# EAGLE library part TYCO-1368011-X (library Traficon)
CT: Connector to replace the 2_stacked_rj45_w_leds (12/03/2008)
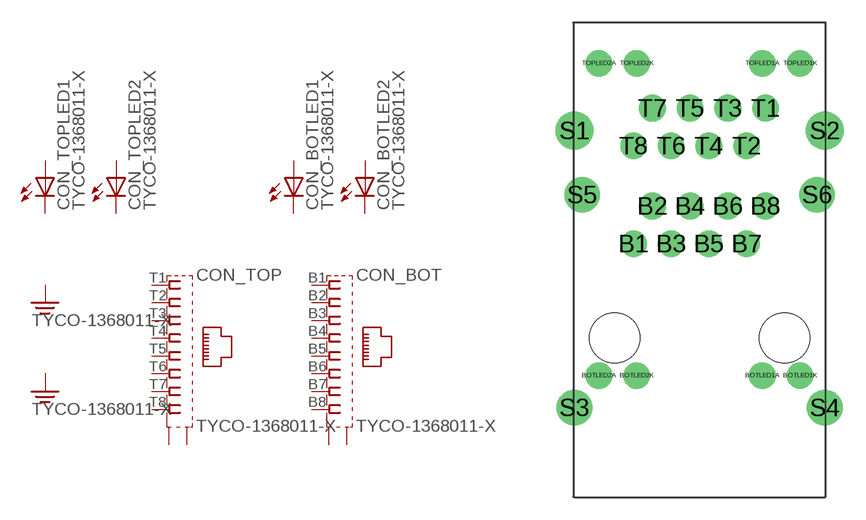
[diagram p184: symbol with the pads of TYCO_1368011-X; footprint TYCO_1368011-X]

Designator prefix CON; gates _BOT=JACK8SH _TOP=JACK8SH _TOPLED1=LED-1 _TOPLED2=LED-1 _BOTLED1=LED-1 _BOTLED2=LED-1 _SH1=PE _SH2=PE

## TYCO-1368011-X  [TYCO_1368011-X]
B1  _BOT:1  pas
B2  _BOT:2  pas
B3  _BOT:3  pas
B4  _BOT:4  pas
B5  _BOT:5  pas
B6  _BOT:6  pas
B7  _BOT:7  pas
B8  _BOT:8  pas
BOTLED1A  _BOTLED1:A  pas
BOTLED1K  _BOTLED1:C  pas
BOTLED2A  _BOTLED2:A  pas
BOTLED2K  _BOTLED2:C  pas
S1  _BOT:S1  pas
S2  _BOT:S2  pas
S3  _TOP:S1  pas
S4  _TOP:S2  pas
T1  _TOP:1  pas
T2  _TOP:2  pas
T3  _TOP:3  pas
T4  _TOP:4  pas
T5  _TOP:5  pas
T6  _TOP:6  pas
T7  _TOP:7  pas
T8  _TOP:8  pas
TOPLED1A  _TOPLED1:A  pas
TOPLED1K  _TOPLED1:C  pas
TOPLED2A  _TOPLED2:A  pas
TOPLED2K  _TOPLED2:C  pas

## Footprint TYCO_1368011-X (pad centres in mm)
drill 1.2 round: B1 1.265,6.35; B2 2.535,8.89; B3 3.805,6.35; B4 5.075,8.89; B5 6.345,6.35; B6 7.615,8.89; B7 8.885,6.35; B8 10.155,8.89; BOTLED1A 9.95,-2.54; BOTLED1K 12.49,-2.54; BOTLED2A -1.06,-2.54; BOTLED2K 1.48,-2.54; T1 10.155,15.49; T2 8.885,12.95; T3 7.615,15.49; T4 6.345,12.95; T5 5.075,15.49; T6 3.805,12.95; T7 2.535,15.49; T8 1.265,12.95; TOPLED1A 9.95,18.51; TOPLED1K 12.49,18.51; TOPLED2A -1.06,18.51; TOPLED2K 1.48,18.51
drill 1.7 round: S1 -2.72,13.971; S2 14.15,13.971
drill 1.6 round: S3 -2.721,-4.699; S4 14.156,-4.702; S5 -2.197,9.65; S6 13.631,9.65
hole 3.4 at 0,0
hole 3.4 at 11.43,0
